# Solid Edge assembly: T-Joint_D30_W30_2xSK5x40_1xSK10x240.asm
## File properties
Author: fknapp
Template: iso metric assembly.asm
Last saved by: fknapp
Revision: 4
Application: Solid Edge
Username: fknapp
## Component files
T-Joint_D30_W30.par
SK Schraube 5x40_ohne_Gewinde.par
SK Schraube 10x240_ohne_Gewinde_22042020.par
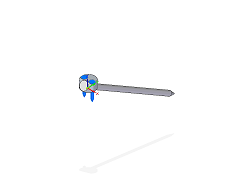
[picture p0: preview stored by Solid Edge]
